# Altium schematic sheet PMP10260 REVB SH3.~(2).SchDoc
size 431 x 279 mm; Date: Not shown in title block; ApprovedBy: Not shown in title block; CheckedBy: Not shown in title block; Author: Not shown in title block; CompanyName: Not shown in title block; Engineer: Not shown in title block; Organization: Not shown in title block; Address1: Not shown in title block; Address2: Not shown in title block; Address3: Not shown in title block; Address4: Not shown in title block; DocumentNumber: 3; Revision: Use project parameter SCH_Rev; SheetNumber: 3; SheetTotal: 3; PageSetup: Record=PageOptions¦CenterHorizontal=True¦CenterVertical=True¦PrintScale=1.00¦XCorrection=1.00¦YCorrection=1.00¦PrintKind=0¦BorderSize=5000000¦LeftOffset=0¦BottomOffset=0¦Orientation=2¦PaperLength=1000¦PaperWidth=1000¦Scale=100¦PaperSource=15¦PrintQuality=600¦MediaType=1¦DitherType=10¦PaperKind=Letter¦PrintScaleMode=1
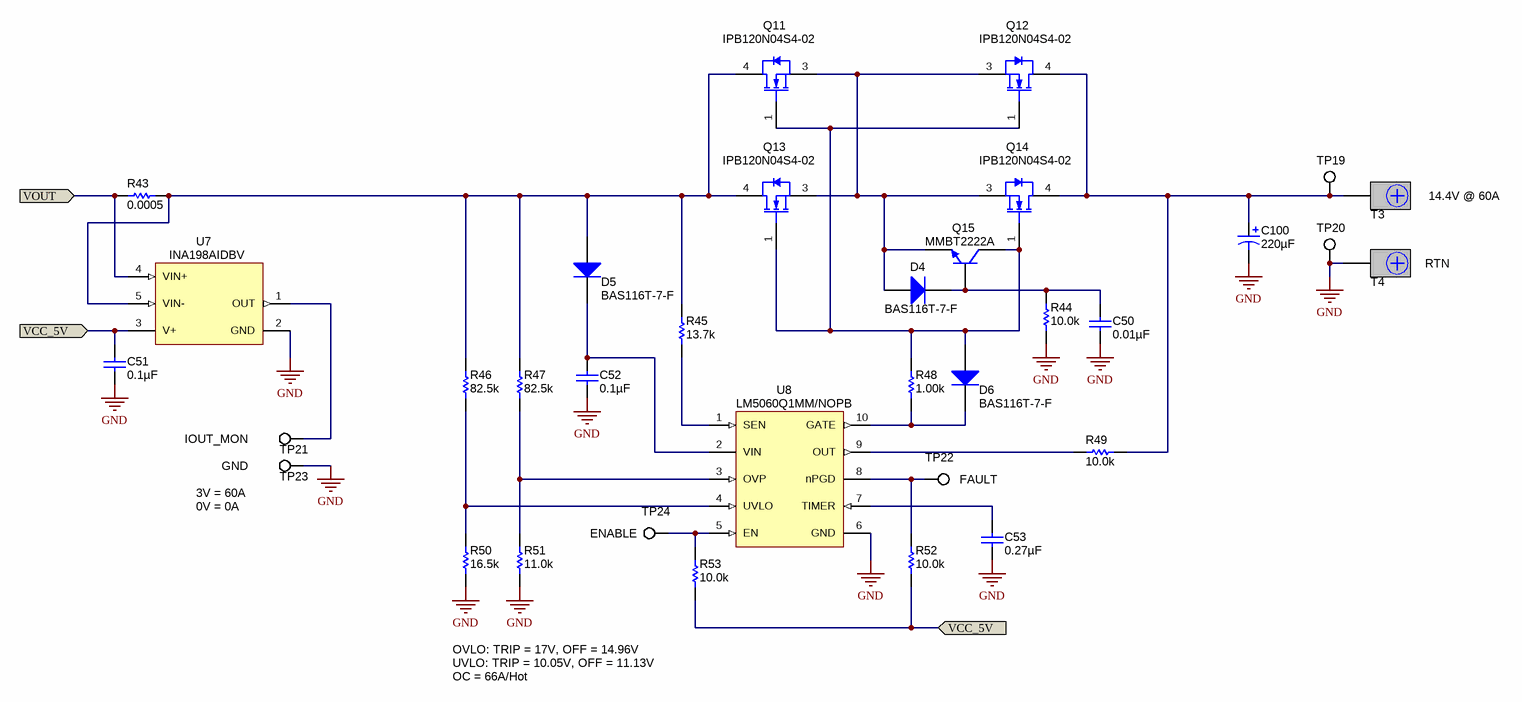
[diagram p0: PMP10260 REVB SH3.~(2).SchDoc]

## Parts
C50  ValueDisplayed: 0.01µF  [0603]  (hidden comment: C1608X7R1H103K)
C51  ValueDisplayed: 0.1µF  [0603]  (hidden comment: C1608X7R1H104K)
C52  ValueDisplayed: 0.1µF  [0603]  (hidden comment: C1608X7R1H104K)
C53  ValueDisplayed: 0.27µF  [0805]  (hidden comment: 0805YC274KAT2A)
C100  ValueDisplayed: 220µF  [ZLJ_800X1150]  (hidden comment: 50ZL220MT78X11.5)
D4  BAS116T-7-F  [SOT-523]
D5  BAS116T-7-F  [SOT-523]
D6  BAS116T-7-F  [SOT-523]
Q11  IPB120N04S4-02  [DDPAK]
Q12  IPB120N04S4-02  [DDPAK]
Q13  IPB120N04S4-02  [DDPAK]
Q14  IPB120N04S4-02  [DDPAK]
Q15  MMBT2222A  [SOT-23]
R43  value 0.0005  [CSS2725_0005]  (hidden comment: CSS2725FTL500)
R44  value 10.0k  [0603]  (hidden comment: CRCW060310K0FKEA)
R45  value 13.7k  [0603]  (hidden comment: CRCW060313K7FKEA)
R46  value 82.5k  [0603]  (hidden comment: CRCW060382K5FKEA)
R47  value 82.5k  [0603]  (hidden comment: CRCW060382K5FKEA)
R48  value 1.00k  [0603]  (hidden comment: CRCW06031K00FKEA)
R49  value 10.0k  [0603]  (hidden comment: CRCW060310K0FKEA)
R50  value 16.5k  [0603]  (hidden comment: CRCW060316K5FKEA)
R51  value 11.0k  [0603]  (hidden comment: CRCW060311K0FKEA)
R52  value 10.0k  [0603]  (hidden comment: CRCW060310K0FKEA)
R53  value 10.0k  [0603]  (hidden comment: CRCW060310K0FKEA)
T3  CB70-14-CY  [CB70-14-CY]  (value not drawn)
T4  CB70-14-CY  [CB70-14-CY]  (value not drawn)
TP19  5015  [Testpoint_Keystone_Miniature]  (value not drawn)
TP20  5015  [Testpoint_Keystone_Miniature]  (value not drawn)
TP21  5015  [Testpoint_Keystone_Miniature]  (value not drawn)
TP22  5015  [Testpoint_Keystone_Miniature]  (value not drawn)
TP23  5015  [Testpoint_Keystone_Miniature]  (value not drawn)
TP24  5015  [Testpoint_Keystone_Miniature]  (value not drawn)
U7  INA198AIDBV  [DBV0005A_N]
U8  LM5060Q1MM/NOPB  [MUB10A_N]

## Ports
VCC_5V, VOUT

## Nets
GND: C50.2 C51.2 C52.2 C53.2 C100.2(-) R44.1 R50.1 R51.1 T4.1 TP20.1 TP23.1 U7.2(GND) U8.6(GND)
VCC_5V: C51.1 R52.1 R53.1 U7.3(V+) ; port VCC_5V
VOUT: R43.1 U7.4(VIN+) ; port VOUT
NetC50_1: C50.1 D4.3(K) Q15.1(B) R44.2
NetC52_1: C52.1 D5.3(K) U8.2(VIN)
NetC53_1: C53.1 U8.7(TIMER)
NetC100_1: C100.1(+) Q12.4(D) Q14.4(D) R49.1 T3.1 TP19.1
NetD4_1: D4.1(A) Q11.3(S) Q12.3(S) Q13.3(S) Q14.3(S) Q15.2(E)
NetD5_1: D5.1(A) Q11.4(D) Q13.4(D) R43.2 R45.2 R46.2 R47.2 U7.5(VIN-)
NetD6_1: D6.1(A) Q11.1(G) Q12.1(G) Q13.1(G) Q14.1(G) Q15.3(C) R48.1
NetD6_3: D6.3(K) R48.2 U8.10(GATE)
NetR45_1: R45.1 U8.1(SEN)
NetR46_1: R46.1 R50.2 U8.4(UVLO)
NetR47_1: R47.1 R51.2 U8.3(OVP)
NetR49_2: R49.2 U8.9(OUT)
NetR52_2: R52.2 TP22.1 U8.8(nPGD)
NetR53_2: R53.2 TP24.1 U8.5(EN)
NetTP21_1: TP21.1 U7.1(OUT)

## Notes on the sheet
- 14.4V @ 60A
- RTN
- IOUT_MON
- GND
- (near TP22) FAULT
- 3V = 60A
- 0V = 0A
- (near TP24) ENABLE
- OVLO: TRIP = 17V, OFF = 14.96V
  UVLO: TRIP = 10.05V, OFF = 11.13V
  OC = 66A/Hot

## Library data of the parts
C50 = C1608X7R1H103K: CAP, CERM, 0.01uF, 50V, +/-10%, X7R, 0603; Manufacturer: TDK; Polarized: N; CompType: Capacitor; U/M: EA; Cap_F: 0.00000001; Tolerance_%: 10; ESR_Ohm: 0.0539; Value1: 0.0539 ohm; VDC_V: 50; TaMin_C: -55; TaMax_C: 125
C51 C52 = C1608X7R1H104K: CAP, CERM, 0.1uF, 50V, +/-10%, X7R, 0603; Manufacturer: TDK; Polarized: N; CompType: Capacitor; U/M: EA; Cap_F: 0.0000001; Tolerance_%: 10; ESR_Ohm: 0.017; Value1: 0.017 ohm; VDC_V: 50; TaMin_C: -55; TaMax_C: 125
C53 = 0805YC274KAT2A: CAP, CERM, 0.27uF, 16V, +/-10%, X7R, 0805; Manufacturer: AVX; Polarized: N; CompType: Capacitor; U/M: EA; Cap_F: 0.00000027; Tolerance_%: 10; ESR_Ohm: 0.015; Value1: 0.015 ohm; VDC_V: 16; TaMin_C: -55; TaMax_C: 125
C100 = 50ZLJ100MT78X11.5: CAP, AL, 220 µF, 50 V, +/- 20%, 0.072 ohm, TH; Manufacturer: Rubycon; Polarized: Y; CompType: Capacitor; Value: 220uF; U/M: EA; Cap_F: 0.0001; Tolerance_%: 20; VDC_V: 50; Value2: 50V; ESR_ohm: 0.12; IRMS_A: 0.95; TaMin_C: -40; TaMax_C: 105; Cap_Case: 8x11.5
D4-D6 = BAS116T-7-F: Diode, Switching, 85V, 0.215A, SOT-523; Manufacturer: Diodes Inc.; U/M: EA; Vf_V: 1.25; Value2: 1.25V; Io_A: 0.215; Vr_V: 85; TJmax_C: 150
Q11-Q14 = IPB100N10S3-05: MOSFET, N-CH, 40V, 120A, DDPAK; Manufacturer: Infineon Technologies; Alternate Manufacturer: None; U/M: EA; ChType: N; VdsMax_V: 40; Value1: ? ohm; Vgs_V: 20; IdsMax_A: 100
Q15 = MMBT2222A, Fairchild Semiconductor: Transistor, NPN, 40V, 0.15A, SOT-23; CompType: BJT; PNP: 0; NPN: 1; Vceo_V: 40; Vcesat1_V: 0.3; Value: 0.3V; IcRated_A: 0.15; HfeMax: 300; TaMin_C: -55; TaMax_C: 150; U/M: EA
R43 = CSS2725FTL500: RES, 0.0005 ohm, 1%, 4W, RES_2725; Manufacturer: Stackpole Electronics Inc; CompType: Resistor; Value_Code: R0005; Tolerance_%: 1; Power_W: 4; TempCo: 50 ppm/C; U/M: EA
R44 R49 R52 R53 = CRCW060310K0FKEA: RES, 10.0k ohm, 1%, 0.1W, 0603; Manufacturer: Vishay-Dale; CompType: Resistor; Res_ohm: 10000; Value_Code: 10k0; Tolerance_%: 1; Power_W: 0.1; VDC_V: 75; TempCo: 100 ppm/C; EIA_Code: E96; U/M: EA
R45 = CRCW060313K7FKEA: RES, 13.7k ohm, 1%, 0.1W, 0603; Manufacturer: Vishay-Dale; CompType: Resistor; Res_ohm: 13700; Value_Code: 13k7; Tolerance_%: 1; Power_W: 0.1; VDC_V: 75; TempCo: 100 ppm/C; EIA_Code: E96; U/M: EA
R46 R47 = CRCW060382K5FKEA: RES, 82.5k ohm, 1%, 0.1W, 0603; Manufacturer: Vishay-Dale; CompType: Resistor; Res_ohm: 82500; Value_Code: 82k5; Tolerance_%: 1; Power_W: 0.1; VDC_V: 75; TempCo: 100 ppm/C; EIA_Code: E96; U/M: EA
R48 = CRCW06031K00FKEA: RES, 1.00k ohm, 1%, 0.1W, 0603; Manufacturer: Vishay-Dale; CompType: Resistor; Res_ohm: 1000; Value_Code: 1k00; Tolerance_%: 1; Power_W: 0.1; VDC_V: 75; TempCo: 100 ppm/C; EIA_Code: E96; U/M: EA
R50 = CRCW060316K5FKEA: RES, 16.5k ohm, 1%, 0.1W, 0603; Manufacturer: Vishay-Dale; CompType: Resistor; Res_ohm: 16500; Value_Code: 16k5; Tolerance_%: 1; Power_W: 0.1; VDC_V: 75; TempCo: 100 ppm/C; EIA_Code: E96; U/M: EA
R51 = CRCW060311K0FKEA: RES, 11.0k ohm, 1%, 0.1W, 0603; Manufacturer: Vishay-Dale; CompType: Resistor; Res_ohm: 11000; Value_Code: 11k0; Tolerance_%: 1; Power_W: 0.1; VDC_V: 75; TempCo: 100 ppm/C; EIA_Code: E96; U/M: EA
T3 T4 = CB70-14-CY: Terminal 90A Lug; Manufacturer: Panduit; SymbolCreator: crossc; CompType: Screw Terminal; U/M: EA
TP19-TP24 = 5015: Test Point, Miniature, SMT; Manufacturer: Keystone; CompType: Test Point Loop; U/M: EA
U7 = INA198AIDBV: CURRENT SHUNT MONITOR -16V to +80V Common-Mode Range, DBV0005A; Alternate Manufacturer: None; Manufacturer: Texas Instruments; SymbolCreator: a0411947; CompType: IC; U/M: EA
U8 = LM5060Q1MM/NOPB: High-Side Protection Controller with Low Quiescent Current, 10-pin MSOP, Pb-Free; Manufacturer: National Semiconductor; PackageTopMarking: ZXTT*SZAB; PowerWise: N; CompType: Switcher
